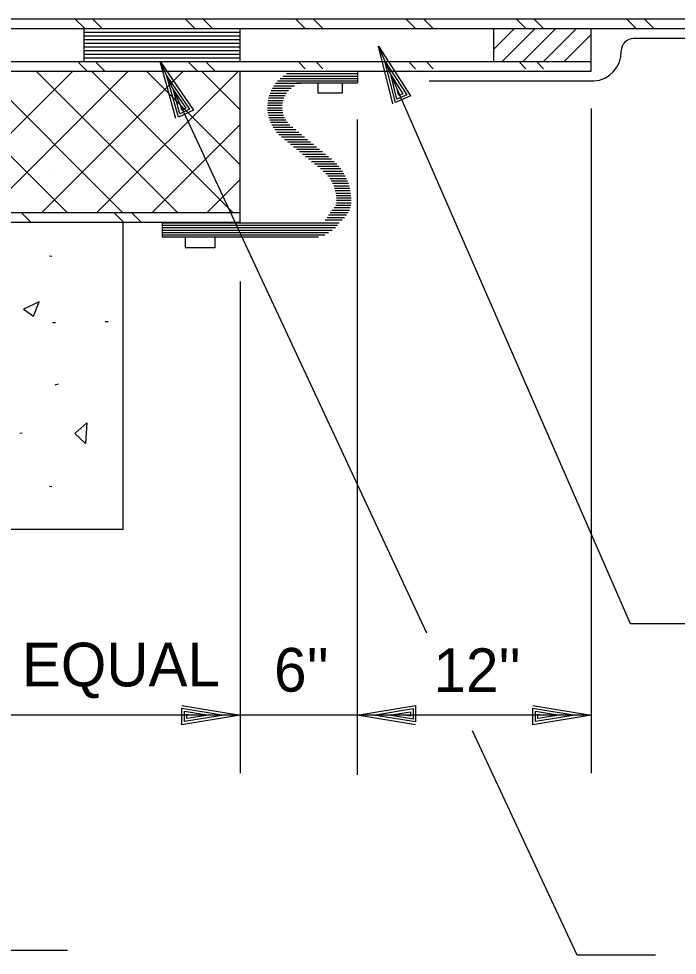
# Model space of a CAD drawing. Extents: x 22422.9 to 22498.9, y 22369.6 to 22415.
# Drawn here: x 22431.684 to 22434.498, y 22388.168 to 22392.17 of the extents above; entities that cross this region are included whole.
import ezdxf

# ---------------------------------------------------------------- set-up
doc = ezdxf.new("R2010")
doc.units = 0
for name, color, linetype in [('Level 1', 7, 'Continuous'), ('Level 2', 7, 'Continuous'), ('Level 4', 7, 'Continuous'), ('Level 44', 7, 'Continuous'), ('Level 7', 7, 'Continuous'), ('Level 8', 7, 'Continuous')]:
    doc.layers.add(name, color=color, linetype=linetype)

msp = doc.modelspace()

# ---------------------------------------------------------------- linework, layer by layer
at = {"layer": 'Level 1'}
for p, q in [((22431.9637, 22392.1123), (22432.6304, 22392.1123)), ((22433.7137, 22392.0396), (22433.8021, 22392.1279)), ((22433.7499, 22391.9873), (22433.8905, 22392.1279)), ((22433.8383, 22391.9873), (22433.9789, 22392.1279)), ((22433.9267, 22391.9873), (22434.0673, 22392.1279)), ((22434.015, 22391.9873), (22434.1304, 22392.1027)), ((22431.9637, 22392.0967), (22432.6304, 22392.0967)), ((22431.9637, 22392.0811), (22432.6304, 22392.0811)), ((22431.9637, 22392.0654), (22432.6304, 22392.0654)), ((22431.9637, 22392.0498), (22432.6304, 22392.0498)), ((22431.9637, 22392.0342), (22432.6304, 22392.0342)), ((22431.1304, 22391.9873), (22434.1304, 22391.9873)), ((22431.9637, 22392.0186), (22432.6304, 22392.0186)), ((22431.9637, 22392.0029), (22432.6304, 22392.0029)), ((22431.1304, 22391.9456), (22434.1304, 22391.9456)), ((22432.6304, 22391.2998), (22432.6304, 22391.9456)), ((22433.8995, 22391.9018), (22433.8995, 22391.9018)), ((22432.962, 22391.896), (22432.962, 22391.853)), ((22433.0656, 22391.896), (22433.0656, 22391.853)), ((22432.962, 22391.853), (22433.0656, 22391.853)), ((22434.1304, 22391.7855), (22434.1304, 22388.946)), ((22433.1304, 22391.7391), (22433.1304, 22388.9384)), ((22431.8047, 22391.5915), (22431.8047, 22391.5915)), ((22431.8346, 22391.5289), (22431.8346, 22391.5289)), ((22431.1304, 22391.3415), (22432.6304, 22391.3415)), ((22431.1304, 22391.2998), (22432.6304, 22391.2998)), ((22432.3942, 22391.2382), (22432.3942, 22391.1905)), ((22432.5216, 22391.2382), (22432.5216, 22391.1905)), ((22432.5216, 22391.1905), (22432.3942, 22391.1905)), ((22432.6304, 22391.0467), (22432.6304, 22388.946)), ((22432.6304, 22389.1938), (22431.1304, 22389.1938)), ((22432.5611, 22389.1938), (22432.5611, 22389.1938)), ((22432.6304, 22389.1938), (22432.6304, 22389.1938)), ((22433.1304, 22389.1938), (22432.6304, 22389.1938)), ((22434.1304, 22389.1938), (22433.1304, 22389.1938)), ((22431.3119, 22388.1894), (22431.8916, 22388.1894))]:
    msp.add_line(p, q, dxfattribs=at)
at = {"layer": 'Level 2'}
for p, q in [((22431.1304, 22392.1696), (22437.8136, 22392.1696)), ((22431.1304, 22392.1279), (22437.7901, 22392.1279)), ((22431.9637, 22391.9873), (22431.9637, 22392.1279)), ((22432.6304, 22391.9873), (22432.6304, 22392.1279)), ((22433.7137, 22391.9873), (22433.7137, 22392.1279)), ((22434.1304, 22391.9456), (22434.1304, 22392.1279)), ((22433.1317, 22391.9456), (22433.1317, 22391.896)), ((22432.8693, 22391.896), (22433.1317, 22391.896)), ((22432.2959, 22391.2998), (22432.2959, 22391.2382)), ((22432.2959, 22391.2382), (22432.9653, 22391.2382))]:
    msp.add_line(p, q, dxfattribs=at)
for points in [[(22434.6451, 22389.5833), (22434.2976, 22389.5833), (22433.2205, 22392.0517)], [(22433.2823, 22391.8066), (22433.2205, 22392.0517), (22433.3581, 22391.8397), (22433.2933, 22391.8114), (22433.2482, 22391.9881), (22433.3416, 22391.8441), (22433.3001, 22391.826), (22433.2749, 22391.9271), (22433.3251, 22391.8486), (22433.308, 22391.8411), (22433.3026, 22391.8635)], [(22432.3554, 22391.7439), (22432.2874, 22391.9873), (22432.4303, 22391.7788), (22432.3663, 22391.749), (22432.3167, 22391.9245), (22432.4137, 22391.7829), (22432.3726, 22391.7637), (22432.3449, 22391.8641), (22432.3971, 22391.7869), (22432.3802, 22391.779), (22432.3742, 22391.8012)], [(22433.4279, 22389.5437), (22432.2874, 22391.9873)], [(22432.8484, 22391.9456), (22433.1304, 22391.9456)], [(22432.7899, 22391.904), (22433.1304, 22391.904)], [(22432.8002, 22391.9144), (22433.1304, 22391.9144)], [(22432.8126, 22391.9248), (22433.1304, 22391.9248)], [(22432.828, 22391.9352), (22433.1304, 22391.9352)], [(22432.7624, 22391.8623), (22432.8365, 22391.8623)], [(22432.7677, 22391.8727), (22432.8474, 22391.8727)], [(22432.7739, 22391.8831), (22432.8627, 22391.8831)], [(22432.7813, 22391.8936), (22432.8894, 22391.8936)], [(22432.7494, 22391.8206), (22432.8133, 22391.8206)], [(22432.7515, 22391.8311), (22432.8169, 22391.8311)], [(22432.7544, 22391.8415), (22432.8218, 22391.8415)], [(22432.758, 22391.8519), (22432.8282, 22391.8519)], [(22432.7469, 22391.7894), (22432.8094, 22391.7894)], [(22432.7471, 22391.7998), (22432.8097, 22391.7998)], [(22432.7479, 22391.8102), (22432.811, 22391.8102)], [(22432.7474, 22391.779), (22432.8102, 22391.779)], [(22432.7486, 22391.7686), (22432.8121, 22391.7686)], [(22432.7504, 22391.7581), (22432.8151, 22391.7581)], [(22432.753, 22391.7477), (22432.8194, 22391.7477)], [(22432.7562, 22391.7373), (22432.825, 22391.7373)], [(22432.7602, 22391.7269), (22432.8324, 22391.7269)], [(22432.7651, 22391.7165), (22432.842, 22391.7165)], [(22432.7709, 22391.7061), (22432.8544, 22391.7061)], [(22432.7777, 22391.6956), (22432.8672, 22391.6956)], [(22432.7858, 22391.6852), (22432.8799, 22391.6852)], [(22432.7953, 22391.6748), (22432.8927, 22391.6748)], [(22432.8066, 22391.6644), (22432.9055, 22391.6644)], [(22432.8194, 22391.654), (22432.9182, 22391.654)], [(22432.8321, 22391.6436), (22432.931, 22391.6436)], [(22432.8449, 22391.6331), (22432.9438, 22391.6331)], [(22432.8577, 22391.6227), (22432.9565, 22391.6227)], [(22432.8704, 22391.6123), (22432.9693, 22391.6123)], [(22432.8832, 22391.6019), (22432.982, 22391.6019)], [(22432.896, 22391.5915), (22432.9948, 22391.5915)], [(22432.9087, 22391.5811), (22433.0076, 22391.5811)], [(22432.9215, 22391.5706), (22433.0203, 22391.5706)], [(22432.9343, 22391.5602), (22433.0322, 22391.5602)], [(22432.947, 22391.5498), (22433.0426, 22391.5498)], [(22432.9598, 22391.5394), (22433.0517, 22391.5394)], [(22432.9726, 22391.529), (22433.0598, 22391.529)], [(22432.9851, 22391.5186), (22433.067, 22391.5186)], [(22432.9959, 22391.5081), (22433.0734, 22391.5081)], [(22433.005, 22391.4977), (22433.0791, 22391.4977)], [(22433.0127, 22391.4873), (22433.0841, 22391.4873)], [(22433.0193, 22391.4769), (22433.0884, 22391.4769)], [(22433.0248, 22391.4665), (22433.0922, 22391.4665)], [(22433.0295, 22391.4561), (22433.0955, 22391.4561)], [(22433.0333, 22391.4456), (22433.0981, 22391.4456)], [(22433.0363, 22391.4352), (22433.1003, 22391.4352)], [(22433.0387, 22391.4248), (22433.102, 22391.4248)], [(22433.0403, 22391.4144), (22433.1032, 22391.4144)], [(22433.0413, 22391.404), (22433.1039, 22391.404)], [(22433.0413, 22391.3831), (22433.1039, 22391.3831)], [(22433.0417, 22391.3936), (22433.1042, 22391.3936)], [(22433.0142, 22391.3415), (22433.091, 22391.3415)], [(22433.0213, 22391.3519), (22433.0968, 22391.3519)], [(22433.031, 22391.3623), (22433.0994, 22391.3623)], [(22433.0382, 22391.3727), (22433.1032, 22391.3727)], [(22432.993, 22391.3102), (22433.0652, 22391.3102)], [(22433.002, 22391.3206), (22433.0755, 22391.3206)], [(22433.0078, 22391.3311), (22433.0846, 22391.3311)], [(22432.2971, 22391.2976), (22433.053, 22391.2976)], [(22432.2971, 22391.2872), (22433.0465, 22391.2872)], [(22432.2971, 22391.2768), (22433.0379, 22391.2768)], [(22432.2971, 22391.2664), (22433.0227, 22391.2664)], [(22432.2971, 22391.2559), (22433.0069, 22391.2559)], [(22432.2971, 22391.2455), (22432.9916, 22391.2455)], [(22432.3811, 22389.2352), (22432.6304, 22389.1938), (22432.3811, 22389.1525), (22432.3811, 22389.2232), (22432.5611, 22389.1938), (22432.3917, 22389.1658), (22432.3917, 22389.2112), (22432.4944, 22389.1938), (22432.4024, 22389.1792), (22432.4024, 22389.1978), (22432.4251, 22389.1938)], [(22433.3797, 22389.1525), (22433.1304, 22389.1938), (22433.3797, 22389.2352), (22433.3797, 22389.1645), (22433.1997, 22389.1938), (22433.3691, 22389.2218), (22433.3691, 22389.1765), (22433.2664, 22389.1938), (22433.3584, 22389.2085), (22433.3584, 22389.1898), (22433.3357, 22389.1938)], [(22433.8811, 22389.2352), (22434.1304, 22389.1938), (22433.8811, 22389.1525), (22433.8811, 22389.2232), (22434.0611, 22389.1938), (22433.8917, 22389.1658), (22433.8917, 22389.2112), (22433.9944, 22389.1938), (22433.9024, 22389.1792), (22433.9024, 22389.1978), (22433.9251, 22389.1938)], [(22434.4053, 22388.1675), (22434.0702, 22388.1675), (22433.6224, 22389.1271)]]:
    msp.add_lwpolyline(points, dxfattribs=at)
at = {"layer": 'Level 44'}
for p, q in [((22431.8252, 22391.1534), (22431.8152, 22391.1551)), ((22431.8412, 22390.8696), (22431.8277, 22390.8696)), ((22432.0652, 22390.8744), (22432.0524, 22390.8744)), ((22431.8519, 22390.6079), (22431.8384, 22390.6041)), ((22431.6989, 22390.3984), (22431.6879, 22390.3974)), ((22431.8252, 22390.1696), (22431.8152, 22390.1714))]:
    msp.add_line(p, q, dxfattribs=at)
for points in [[(22431.7467, 22390.8989), (22431.7704, 22390.9601), (22431.7042, 22390.9279)], [(22431.9692, 22390.3544), (22431.9229, 22390.3971), (22431.9742, 22390.4429)]]:
    msp.add_lwpolyline(points, close=True, dxfattribs=at)
at = {"layer": 'Level 7'}
for p, q in [((22434.3109, 22392.0863), (22434.6581, 22392.0863)), ((22433.4371, 22391.904), (22434.1408, 22391.904)), ((22432.1304, 22389.9873), (22432.1304, 22391.2998)), ((22432.1304, 22389.9873), (22430.6929, 22389.9873))]:
    msp.add_line(p, q, dxfattribs=at)
for centre, radius, start, end in [((22434.3109, 22392.0316), 0.0529, 90, 180), ((22434.1356, 22392.0264), 0.1225, 272.4366, 2.4366)]:
    msp.add_arc(centre, radius, start, end, dxfattribs=at)
at = {"layer": 'Level 8'}
for p, q in [((22433.2205, 22392.0517), (22433.2205, 22392.0517)), ((22432.2874, 22391.9873), (22432.2874, 22391.9873)), ((22433.2482, 22391.9881), (22433.2482, 22391.9881)), ((22432.3167, 22391.9245), (22432.3167, 22391.9245)), ((22432.5611, 22389.1938), (22432.5611, 22389.1938)), ((22432.6304, 22389.1938), (22432.6304, 22389.1938)), ((22433.1304, 22389.1938), (22433.1304, 22389.1938)), ((22433.1997, 22389.1938), (22433.1997, 22389.1938)), ((22434.0611, 22389.1938), (22434.0611, 22389.1938)), ((22434.1304, 22389.1938), (22434.1304, 22389.1938))]:
    msp.add_line(p, q, dxfattribs=at)
for points in [[(22431.9654, 22392.1279), (22431.9238, 22392.1696)], [(22432.0408, 22392.1279), (22431.9992, 22392.1696)], [(22432.4368, 22392.1279), (22432.3952, 22392.1696)], [(22432.5123, 22392.1279), (22432.4706, 22392.1696)], [(22432.9082, 22392.1279), (22432.8666, 22392.1696)], [(22432.9837, 22392.1279), (22432.942, 22392.1696)], [(22433.3796, 22392.1279), (22433.338, 22392.1696)], [(22433.4551, 22392.1279), (22433.4134, 22392.1696)], [(22433.851, 22392.1279), (22433.8094, 22392.1696)], [(22433.9265, 22392.1279), (22433.8848, 22392.1696)], [(22434.3225, 22392.1279), (22434.2808, 22392.1696)], [(22434.3979, 22392.1279), (22434.3562, 22392.1696)], [(22431.9758, 22391.9456), (22431.9394, 22391.9821)], [(22432.0513, 22391.9456), (22432.0148, 22391.9821)], [(22432.4472, 22391.9456), (22432.4108, 22391.9821)], [(22432.5227, 22391.9456), (22432.4862, 22391.9821)], [(22432.9082, 22391.9561), (22432.8822, 22391.9821)], [(22432.9837, 22391.9561), (22432.9576, 22391.9821)], [(22433.3796, 22391.9561), (22433.3536, 22391.9821)], [(22433.4551, 22391.9561), (22433.429, 22391.9821)], [(22433.851, 22391.9561), (22433.825, 22391.9821)], [(22433.9265, 22391.9561), (22433.9004, 22391.9821)], [(22431.891, 22391.3415), (22431.2868, 22391.9456)], [(22431.3108, 22391.3415), (22431.915, 22391.9456)], [(22432.1267, 22391.3415), (22431.5225, 22391.9456)], [(22431.5465, 22391.3415), (22432.1507, 22391.9456)], [(22432.3624, 22391.3415), (22431.7582, 22391.9456)], [(22431.7822, 22391.3415), (22432.3864, 22391.9456)], [(22432.5981, 22391.3415), (22431.9939, 22391.9456)], [(22432.0179, 22391.3415), (22432.6221, 22391.9456)], [(22432.6304, 22391.5449), (22432.2296, 22391.9456)], [(22432.6304, 22391.7805), (22432.4653, 22391.9456)], [(22432.2536, 22391.3415), (22432.6304, 22391.7183)], [(22432.4893, 22391.3415), (22432.6304, 22391.4826)], [(22431.7358, 22391.2998), (22431.6941, 22391.3415)], [(22432.1318, 22391.2998), (22432.0901, 22391.3415)], [(22432.2072, 22391.2998), (22432.1655, 22391.3415)]]:
    msp.add_lwpolyline(points, dxfattribs=at)

# ---------------------------------------------------------------- texts
at = {"layer": 'Level 4'}
for s, p in [('EQUAL', (22431.6973, 22389.3165)), ("6''", (22432.7748, 22389.2942)), ("12''", (22433.4561, 22389.2924))]:
    msp.add_text(s, height=0.18667, dxfattribs=at).set_placement(p)

doc.saveas('drawing.dxf')
